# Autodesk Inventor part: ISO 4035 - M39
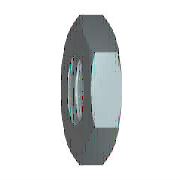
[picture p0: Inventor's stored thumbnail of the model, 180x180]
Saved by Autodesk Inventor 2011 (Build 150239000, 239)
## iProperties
IsCustomPart: 0
Created: 2010-02
Part Number: ISO 4035 - M39
Material: Stainless Steel, 440C
Description: Hexagon thin nuts (chamfered) - Product grades A and B
Document SubType Name: Modeling
Standard: ISO 4035
Designer: HTYCOON
Standard Revision: Third edition 1999-08-15
Standards Organization: ISO
Language: en-US
Size Designation: M39
Categories: <MemberInstance><Categories><Category DisplayName="Fasteners" InternalName="e4da775c-781d-43d5-af7c-5136215cf5a6" Mnemonic="FSTN"><Category DisplayName="Nuts" I
Density: 7.75 g/cm^3
Author: HTYCOON
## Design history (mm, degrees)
workaxis "Work Axis1"
workplane "Work Plane1"
sketch "Sketch1"
  geometry: L1 (-34.641, 0)-(-17.321, 30); L2 (-17.321, 30)-(17.321, 30); L3 (17.321, 30)-(34.641, 0); L4 (34.641, 0)-(17.321, -30); L5 (17.321, -30)-(-17.321, -30); L6 (-17.321, -30)-(-34.641, 0); 2 further points
  constraints: 12 end point, 1 coincident, 1 horizontal, 11 other
  dimensions: "d0" = 69.28203 distance of L3.end L1.start (= 1.1547 x SW)
extrude "Body" new body sketch "Sketch1" distance "d1" = 19.5 (= KOH); taper "d2" = 0 deg
revolve "Chamfer1" stored, may be unused: angle "d7" = 90 deg
sketch "Sketch3"
  geometry: 4 further points
  constraints: 1 coincident, 1 other
hole "Thread" sketch "Sketch3" diameter "d25" = 34.66987; stored, may be unused: countersink angle "d29" = 82 deg, drill point angle "d31" = 118 deg; dims "d26" = 6, "d27" = 4, "d28" = 2, "d30" = 8
body "Solid1"
chamfer "Chamfer2" distance "d8" = 2.16506 (= -0.5 x GD1 + 0.5 x NND); stored, may be unused: angle "d9" = 30 deg, second distance "d40" = 2.16506 (= -0.5 x GD1 + 0.5 x NND)
chamfer "Chamfer3" distance "d10" = 2.16506 (= -0.5 x GD1 + 0.5 x NND); stored, may be unused: angle "d11" = 30 deg, second distance "d41" = 2.16506 (= -0.5 x GD1 + 0.5 x NND)
sketch "Sketch2"
  geometry: L1 (0, 17.321)-(0, 34.641) reference; L2 (0, 34.641)-(19.5, 34.641) reference; L3 (19.5, 17.321)-(19.5, 34.641) reference; L4 (-3.9, 0)-(23.4, 0) reference; L5 (3.863, 34.641)-(0, 27.95); L6 (15.637, 34.641)-(19.5, 27.95)
  constraints: 4 end point, 4 point on line
  dimensions: "d3" = 30 deg angle of L1 L5 (= ANG1); "d4" = 30 deg angle of L3 L6 (= ANG2); "d5" = 55.9 diameter of L5.end L4 (= SW0); "d6" = 55.9 diameter of L6.end L4 (= SW01)
other parameters: "ANG1" = 30 deg [user parameter; used in 1 equation term], "ANG2" = 30 deg [user parameter; used in 1 equation term], "NND" = 39 [user parameter; used in 4 equation terms], "KOH" = 19.5 [user parameter; used in 1 equation term], "SW0" = 55.9 [user parameter; used in 2 equation terms], "SW01" = 55.9 (= SW0) [user parameter; used in 1 equation term], "GD1" = 34.66987 (computed from THREADDIA, PTC, TOA) [user parameter; used in 4 equation terms], "d13" = 0, "d14" = 0, "d39" = 0, "d42" = 0, "GUL" = 2.16506 (= 0.541266 x PTC) [user parameter], "TPU" = 2.5 (computed from PTC) [user parameter], "THREADDIA" = 39 [user parameter; used in 1 equation term], "TOA" = 30 deg [user parameter; used in 1 equation term], "PTC" = 4 [user parameter; used in 4 equation terms], "E0" = 69.3 (= 1.155 x SW) [user parameter], "GAL" = 2.16506 (= 0.541266 x PTC) [user parameter]
